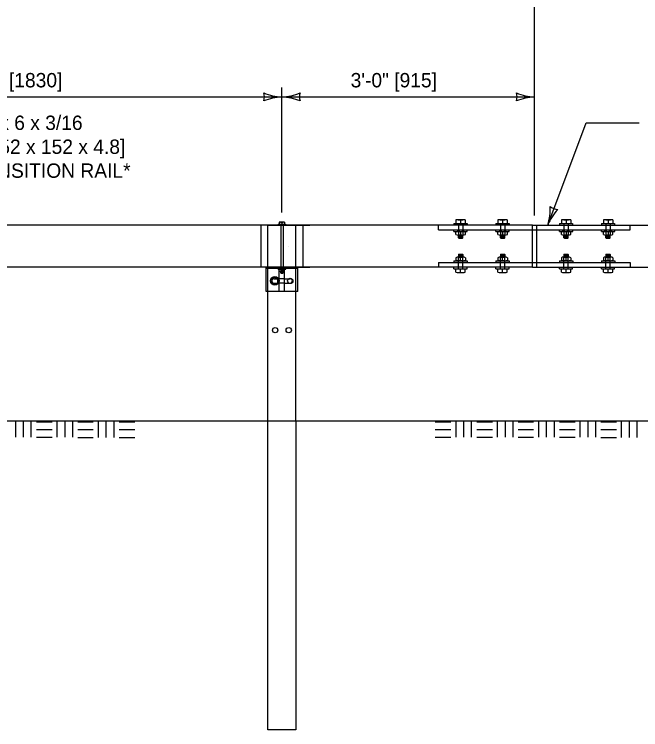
# Model space of a CAD drawing. Extents: x 49983 to 50021, y 49963.5 to 50011.4.
# Drawn here: x 50011.337 to 50013.953, y 49993.178 to 49996.167 of the extents above; entities that cross this region are included whole.
import ezdxf

# ---------------------------------------------------------------- set-up
doc = ezdxf.new("R2010")
doc.units = 0
for name, color, linetype in [('Level 1', 7, 'Continuous'), ('Level 10', 7, 'Continuous'), ('Level 2', 7, 'Continuous'), ('Level 3', 7, 'Continuous'), ('Level 4', 7, 'Continuous')]:
    doc.layers.add(name, color=color, linetype=linetype)

msp = doc.modelspace()

# ---------------------------------------------------------------- linework, layer by layer
at = {"layer": 'Level 1'}
for p, q in [((50013.1811, 49995.3074), (50013.1811, 49995.2927)), ((50013.1908, 49995.3086), (50013.2104, 49995.3086)), ((50013.2006, 49995.3074), (50013.2006, 49995.2927)), ((50013.2202, 49995.3074), (50013.2202, 49995.2927)), ((50013.3564, 49995.3074), (50013.3564, 49995.2927)), ((50013.3662, 49995.3086), (50013.3857, 49995.3086)), ((50013.376, 49995.3074), (50013.376, 49995.2927)), ((50013.3955, 49995.3074), (50013.3955, 49995.2927)), ((50013.6214, 49995.3074), (50013.6214, 49995.2927)), ((50013.6311, 49995.3086), (50013.6507, 49995.3086)), ((50013.6409, 49995.3074), (50013.6409, 49995.2927)), ((50013.6605, 49995.3074), (50013.6605, 49995.2927)), ((50013.7967, 49995.3074), (50013.7967, 49995.2927)), ((50013.8065, 49995.3086), (50013.826, 49995.3086)), ((50013.8163, 49995.3074), (50013.8163, 49995.2927)), ((50013.8358, 49995.3074), (50013.8358, 49995.2927)), ((50013.5013, 49995.2862), (50005.468, 49995.2862)), ((50012.3959, 49995.2862), (50012.5716, 49995.2862)), ((50012.5414, 49995.2862), (50012.4261, 49995.2862)), ((50012.4389, 49995.2899), (50012.4701, 49995.2899)), ((50012.4389, 49995.2899), (50012.4389, 49995.2862)), ((50012.4436, 49995.2981), (50012.4436, 49995.2899)), ((50012.4491, 49995.2988), (50012.4601, 49995.2988)), ((50012.4546, 49995.2981), (50012.4546, 49995.2899)), ((50012.4656, 49995.2981), (50012.4656, 49995.2899)), ((50012.4701, 49995.2899), (50012.4701, 49995.2862)), ((50013.1727, 49995.2927), (50013.2282, 49995.2927)), ((50013.1727, 49995.2927), (50013.1727, 49995.2862)), ((50013.2282, 49995.2927), (50013.2282, 49995.2862)), ((50013.348, 49995.2927), (50013.4035, 49995.2927)), ((50013.348, 49995.2927), (50013.348, 49995.2862)), ((50013.4035, 49995.2927), (50013.4035, 49995.2862)), ((50013.5013, 49995.2862), (50015.1856, 49995.2862)), ((50013.5013, 49995.1105), (50013.5013, 49995.2862)), ((50013.5179, 49995.2862), (50013.5179, 49995.1105)), ((50013.613, 49995.2927), (50013.6685, 49995.2927)), ((50013.613, 49995.2927), (50013.613, 49995.2862)), ((50013.6685, 49995.2927), (50013.6685, 49995.2862)), ((50013.7883, 49995.2927), (50013.8438, 49995.2927)), ((50013.7883, 49995.2927), (50013.7883, 49995.2862)), ((50013.8438, 49995.2927), (50013.8438, 49995.2862)), ((50013.5013, 49995.2666), (50013.5179, 49995.2666)), ((50013.5013, 49995.1302), (50013.5179, 49995.1302)), ((50013.5013, 49995.1105), (50005.468, 49995.1105)), ((50012.3887, 49995.008), (50012.3887, 49995.1105)), ((50012.5205, 49995.105), (50012.3887, 49995.105)), ((50012.3959, 49995.1105), (50012.5716, 49995.1105)), ((50012.4388, 49995.1014), (50012.4388, 49995.1051)), ((50012.4388, 49995.1014), (50012.4703, 49995.1014)), ((50012.4398, 49995.1105), (50012.5716, 49995.1105)), ((50012.4436, 49995.1014), (50012.4436, 49995.0998)), ((50012.4436, 49995.0942), (50012.4436, 49995.0997)), ((50012.4547, 49995.0997), (50012.4547, 49995.0942)), ((50012.4656, 49995.1014), (50012.4656, 49995.0998)), ((50012.4657, 49995.0942), (50012.4657, 49995.0997)), ((50012.4703, 49995.1014), (50012.4703, 49995.1051)), ((50012.5205, 49995.008), (50012.5205, 49995.1105)), ((50013.1727, 49995.104), (50013.1727, 49995.1105)), ((50013.1727, 49995.104), (50013.2282, 49995.104)), ((50013.1811, 49995.0894), (50013.1811, 49995.104)), ((50013.2006, 49995.0894), (50013.2006, 49995.104)), ((50013.2202, 49995.0894), (50013.2202, 49995.104)), ((50013.2282, 49995.104), (50013.2282, 49995.1105)), ((50013.348, 49995.104), (50013.348, 49995.1105)), ((50013.348, 49995.104), (50013.4035, 49995.104)), ((50013.3564, 49995.0894), (50013.3564, 49995.104)), ((50013.376, 49995.0894), (50013.376, 49995.104)), ((50013.3955, 49995.0894), (50013.3955, 49995.104)), ((50013.4035, 49995.104), (50013.4035, 49995.1105)), ((50013.5013, 49995.1105), (50015.1856, 49995.1105)), ((50013.613, 49995.104), (50013.613, 49995.1105)), ((50013.613, 49995.104), (50013.6685, 49995.104)), ((50013.6214, 49995.0894), (50013.6214, 49995.104)), ((50013.6409, 49995.0894), (50013.6409, 49995.104)), ((50013.6605, 49995.0894), (50013.6605, 49995.104)), ((50013.6685, 49995.104), (50013.6685, 49995.1105)), ((50013.7883, 49995.104), (50013.7883, 49995.1105)), ((50013.7883, 49995.104), (50013.8438, 49995.104)), ((50013.7967, 49995.0894), (50013.7967, 49995.104)), ((50013.8163, 49995.0894), (50013.8163, 49995.104)), ((50013.8358, 49995.0894), (50013.8358, 49995.104)), ((50013.8438, 49995.104), (50013.8438, 49995.1105)), ((50012.425, 49995.0678), (50012.4119, 49995.0601)), ((50012.4382, 49995.0601), (50012.425, 49995.0678)), ((50012.4436, 49995.008), (50012.4436, 49995.0941)), ((50012.4491, 49995.0925), (50012.4602, 49995.0925)), ((50012.4495, 49995.0864), (50012.4495, 49995.0925)), ((50012.4598, 49995.0864), (50012.4495, 49995.0864)), ((50012.4495, 49995.0864), (50012.4505, 49995.0853)), ((50012.4505, 49995.0853), (50012.4588, 49995.0853)), ((50012.451, 49995.091), (50012.4582, 49995.091)), ((50012.451, 49995.09), (50012.4582, 49995.09)), ((50012.451, 49995.089), (50012.4582, 49995.089)), ((50012.451, 49995.0879), (50012.4582, 49995.0879)), ((50012.4598, 49995.0864), (50012.4588, 49995.0853)), ((50012.4598, 49995.0864), (50012.4598, 49995.0925)), ((50012.4656, 49995.008), (50012.4656, 49995.0941)), ((50013.1908, 49995.0882), (50013.2104, 49995.0882)), ((50013.3662, 49995.0882), (50013.3857, 49995.0882)), ((50013.6311, 49995.0882), (50013.6507, 49995.0882)), ((50013.8065, 49995.0882), (50013.826, 49995.0882)), ((50012.4119, 49995.0601), (50012.4119, 49995.0453)), ((50012.4119, 49995.0453), (50012.425, 49995.0382)), ((50012.425, 49995.0382), (50012.4382, 49995.0453)), ((50012.4382, 49995.0453), (50012.4382, 49995.0601)), ((50012.4406, 49995.0437), (50012.4436, 49995.0437)), ((50012.4409, 49995.062), (50012.4436, 49995.062)), ((50012.4656, 49995.062), (50012.4889, 49995.062)), ((50012.4656, 49995.0437), (50012.4894, 49995.0437)), ((50012.5205, 49995.008), (50012.3887, 49995.008)), ((50012.3959, 49994.4663), (50012.3959, 49995.008)), ((50012.513, 49994.4663), (50012.513, 49995.008)), ((50015.1755, 49994.4663), (50005.1046, 49994.4663)), ((50011.3431, 49994.3995), (50011.3431, 49994.4645)), ((50011.3756, 49994.3995), (50011.3756, 49994.4645)), ((50011.4081, 49994.3995), (50011.4081, 49994.4645)), ((50011.4297, 49994.4645), (50011.4948, 49994.4645)), ((50011.5165, 49994.3995), (50011.5165, 49994.4645)), ((50011.5489, 49994.3995), (50011.5489, 49994.4645)), ((50011.5814, 49994.3995), (50011.5814, 49994.4645)), ((50011.602, 49994.4643), (50011.667, 49994.4643)), ((50011.6887, 49994.3993), (50011.6887, 49994.4643)), ((50011.7212, 49994.3993), (50011.7212, 49994.4643)), ((50011.7537, 49994.3993), (50011.7537, 49994.4643)), ((50011.7753, 49994.4643), (50011.8404, 49994.4643)), ((50013.0951, 49994.4646), (50013.1601, 49994.4646)), ((50013.1818, 49994.3996), (50013.1818, 49994.4646)), ((50013.2143, 49994.3996), (50013.2143, 49994.4646)), ((50013.2468, 49994.3996), (50013.2468, 49994.4646)), ((50013.2684, 49994.4646), (50013.3335, 49994.4646)), ((50013.3552, 49994.3996), (50013.3552, 49994.4646)), ((50013.3876, 49994.3996), (50013.3876, 49994.4646)), ((50013.4201, 49994.3996), (50013.4201, 49994.4646)), ((50013.4404, 49994.4645), (50013.5054, 49994.4645)), ((50013.5271, 49994.3995), (50013.5271, 49994.4645)), ((50013.5596, 49994.3995), (50013.5596, 49994.4645)), ((50013.5921, 49994.3995), (50013.5921, 49994.4645)), ((50013.6137, 49994.4645), (50013.6788, 49994.4645)), ((50013.7005, 49994.3995), (50013.7005, 49994.4645)), ((50013.7329, 49994.3995), (50013.7329, 49994.4645)), ((50013.7654, 49994.3995), (50013.7654, 49994.4645)), ((50013.786, 49994.4643), (50013.851, 49994.4643)), ((50013.8727, 49994.3993), (50013.8727, 49994.4643)), ((50013.9052, 49994.3993), (50013.9052, 49994.4643)), ((50013.9377, 49994.3993), (50013.9377, 49994.4643)), ((50011.4297, 49994.432), (50011.4948, 49994.432)), ((50011.602, 49994.4318), (50011.667, 49994.4318)), ((50011.7753, 49994.4318), (50011.8404, 49994.4318)), ((50013.0951, 49994.4321), (50013.1601, 49994.4321)), ((50013.2684, 49994.4321), (50013.3335, 49994.4321)), ((50013.4404, 49994.432), (50013.5054, 49994.432)), ((50013.6137, 49994.432), (50013.6788, 49994.432)), ((50013.786, 49994.4318), (50013.851, 49994.4318)), ((50011.4297, 49994.3995), (50011.4948, 49994.3995)), ((50011.602, 49994.3993), (50011.667, 49994.3993)), ((50011.7753, 49994.3993), (50011.8404, 49994.3993)), ((50013.0951, 49994.3996), (50013.1601, 49994.3996)), ((50013.2684, 49994.3996), (50013.3335, 49994.3996)), ((50013.4404, 49994.3995), (50013.5054, 49994.3995)), ((50013.6137, 49994.3995), (50013.6788, 49994.3995)), ((50013.786, 49994.3993), (50013.851, 49994.3993))]:
    msp.add_line(p, q, dxfattribs=at)
for centre, radius in [((50012.4252, 49995.0531), 0.0181), ((50012.4263, 49994.847), 0.011)]:
    msp.add_circle(centre, radius, dxfattribs=at)
for centre, radius, start, end in [((50013.1908, 49995.2675), 0.0411, 76.2307, 103.7693), ((50013.2104, 49995.2675), 0.0411, 76.2307, 103.7693), ((50013.3662, 49995.2675), 0.0411, 76.2307, 103.7693), ((50013.3857, 49995.2675), 0.0411, 76.2307, 103.7693), ((50013.6311, 49995.2675), 0.0411, 76.2307, 103.7693), ((50013.6507, 49995.2675), 0.0411, 76.2307, 103.7693), ((50013.8065, 49995.2675), 0.0411, 76.2307, 103.7693), ((50013.826, 49995.2675), 0.0411, 76.2307, 103.7693), ((50012.4491, 49995.2757), 0.0231, 76.2307, 103.7693), ((50012.4601, 49995.2757), 0.0231, 76.2307, 103.7693), ((50012.4491, 49995.0916), 0.00981, 55.616, 124.384), ((50012.4602, 49995.0916), 0.00981, 55.616, 124.384), ((50012.4491, 49995.1023), 0.00981, 235.616, 304.384), ((50012.4602, 49995.1023), 0.00981, 235.616, 304.384), ((50013.1908, 49995.1293), 0.0411, 256.2307, 283.7693), ((50013.2104, 49995.1293), 0.0411, 256.2307, 283.7693), ((50013.3662, 49995.1293), 0.0411, 256.2307, 283.7693), ((50013.3857, 49995.1293), 0.0411, 256.2307, 283.7693), ((50013.6311, 49995.1293), 0.0411, 256.2307, 283.7693), ((50013.6507, 49995.1293), 0.0411, 256.2307, 283.7693), ((50013.8065, 49995.1293), 0.0411, 256.2307, 283.7693), ((50013.826, 49995.1293), 0.0411, 256.2307, 283.7693), ((50012.4894, 49995.0528), 0.00916, 270, 93.2408)]:
    msp.add_arc(centre, radius, start, end, dxfattribs=at)
at = {"layer": 'Level 10'}
for p, q in [((50012.3959, 49995.008), (50012.3959, 49995.2862)), ((50012.4495, 49995.2899), (50012.4495, 49995.0925)), ((50012.4597, 49995.2899), (50012.4597, 49995.0925)), ((50012.513, 49995.008), (50012.513, 49995.2862)), ((50012.4837, 49995.1984), (50012.4837, 49995.1984)), ((50012.4837, 49995.1984), (50012.4837, 49995.1984)), ((50012.4436, 49995.1014), (50012.4436, 49995.105)), ((50012.4656, 49995.1014), (50012.4656, 49995.105)), ((50012.4198, 49995.0437), (50012.4406, 49995.0437)), ((50012.4203, 49995.062), (50012.4409, 49995.062)), ((50012.4656, 49995.062), (50012.4436, 49995.062)), ((50012.4656, 49995.0437), (50012.4436, 49995.0437))]:
    msp.add_line(p, q, dxfattribs=at)
for centre in [(50012.4894, 49995.0528), (50012.483, 49994.847)]:
    msp.add_circle(centre, 0.011, dxfattribs=at)
msp.add_arc((50012.4198, 49995.0528), 0.00916, 86.7592, 270, dxfattribs=at)
at = {"layer": 'Level 3'}
for p, q in [((50013.5096, 49995.3262), (50013.5096, 49997.0642)), ((50012.4546, 49995.3388), (50012.4546, 49995.8615)), ((50010.3461, 49995.8215), (50012.4546, 49995.8215)), ((50012.4546, 49995.8215), (50013.5096, 49995.8215)), ((50013.5643, 49995.2862), (50013.7246, 49995.7136)), ((50013.7246, 49995.7136), (50013.9458, 49995.7136))]:
    msp.add_line(p, q, dxfattribs=at)
for centre, radius, start, end in [((50012.4638, 49996.0437), 0.2223, 247.456, 267.6395), ((50012.3264, 49995.8215), 0.0548, 342.1388, 17.8612), ((50012.4661, 49995.5888), 0.233, 92.8273, 112.0772), ((50012.4431, 49996.0543), 0.233, 272.8273, 292.0772), ((50012.4455, 49995.5994), 0.2223, 67.456, 87.6395), ((50012.5828, 49995.8215), 0.0548, 162.1388, 197.8612), ((50013.5188, 49996.0437), 0.2223, 247.456, 267.6395), ((50013.3814, 49995.8215), 0.0548, 342.1388, 17.8612), ((50013.5211, 49995.5888), 0.233, 92.8273, 112.0772), ((50013.3423, 49995.3572), 0.233, 342.2587, 1.5085), ((50013.769, 49995.1996), 0.2223, 136.8874, 157.0709), ((50013.6093, 49995.4063), 0.0548, 231.5702, 267.2925)]:
    msp.add_arc(centre, radius, start, end, dxfattribs=at)
at = {"layer": 'Level 4'}
for p, q in [((50012.3668, 49995.2862), (50012.3668, 49995.1105)), ((50012.5425, 49995.2862), (50012.5425, 49995.1105)), ((50013.1083, 49995.2665), (50013.1083, 49995.2862)), ((50013.1917, 49995.2927), (50013.1917, 49995.2441)), ((50013.2099, 49995.2927), (50013.2099, 49995.2441)), ((50013.367, 49995.2927), (50013.367, 49995.2441)), ((50013.3853, 49995.2927), (50013.3853, 49995.2441)), ((50013.632, 49995.2927), (50013.632, 49995.2441)), ((50013.6502, 49995.2927), (50013.6502, 49995.2441)), ((50013.8073, 49995.2927), (50013.8073, 49995.2441)), ((50013.8256, 49995.2927), (50013.8256, 49995.2441)), ((50013.909, 49995.2665), (50013.909, 49995.2862)), ((50013.1082, 49995.2666), (50013.5013, 49995.2666)), ((50013.1727, 49995.26), (50013.1727, 49995.2666)), ((50013.1727, 49995.26), (50013.2285, 49995.26)), ((50013.1811, 49995.2471), (50013.1811, 49995.257)), ((50013.2008, 49995.257), (50013.2008, 49995.2471)), ((50013.2205, 49995.2471), (50013.2205, 49995.257)), ((50013.2285, 49995.26), (50013.2285, 49995.2666)), ((50013.348, 49995.26), (50013.348, 49995.2666)), ((50013.348, 49995.26), (50013.4039, 49995.26)), ((50013.3565, 49995.2471), (50013.3565, 49995.257)), ((50013.3762, 49995.257), (50013.3762, 49995.2471)), ((50013.3958, 49995.2471), (50013.3958, 49995.257)), ((50013.4039, 49995.26), (50013.4039, 49995.2666)), ((50013.5179, 49995.2666), (50013.909, 49995.2666)), ((50013.613, 49995.26), (50013.613, 49995.2666)), ((50013.613, 49995.26), (50013.6688, 49995.26)), ((50013.6214, 49995.2471), (50013.6214, 49995.257)), ((50013.6411, 49995.257), (50013.6411, 49995.2471)), ((50013.6608, 49995.2471), (50013.6608, 49995.257)), ((50013.6688, 49995.26), (50013.6688, 49995.2666)), ((50013.7883, 49995.26), (50013.7883, 49995.2666)), ((50013.7883, 49995.26), (50013.8442, 49995.26)), ((50013.7968, 49995.2471), (50013.7968, 49995.257)), ((50013.8165, 49995.257), (50013.8165, 49995.2471)), ((50013.8361, 49995.2471), (50013.8361, 49995.257)), ((50013.8442, 49995.26), (50013.8442, 49995.2666)), ((50013.191, 49995.2441), (50013.2107, 49995.2441)), ((50013.1917, 49995.2332), (50013.1917, 49995.2441)), ((50013.2099, 49995.2332), (50013.1917, 49995.2332)), ((50013.1917, 49995.2332), (50013.1935, 49995.2314)), ((50013.1935, 49995.2314), (50013.2081, 49995.2314)), ((50013.1943, 49995.2415), (50013.2072, 49995.2415)), ((50013.1943, 49995.2397), (50013.2072, 49995.2397)), ((50013.1943, 49995.2378), (50013.2072, 49995.2378)), ((50013.1943, 49995.236), (50013.2072, 49995.236)), ((50013.2099, 49995.2332), (50013.2081, 49995.2314)), ((50013.2099, 49995.2332), (50013.2099, 49995.2441)), ((50013.3663, 49995.2441), (50013.386, 49995.2441)), ((50013.367, 49995.2332), (50013.367, 49995.2441)), ((50013.3853, 49995.2332), (50013.367, 49995.2332)), ((50013.367, 49995.2332), (50013.3689, 49995.2314)), ((50013.3689, 49995.2314), (50013.3835, 49995.2314)), ((50013.3697, 49995.2415), (50013.3825, 49995.2415)), ((50013.3697, 49995.2397), (50013.3825, 49995.2397)), ((50013.3697, 49995.2378), (50013.3825, 49995.2378)), ((50013.3697, 49995.236), (50013.3825, 49995.236)), ((50013.3853, 49995.2332), (50013.3835, 49995.2314)), ((50013.3853, 49995.2332), (50013.3853, 49995.2441)), ((50013.6313, 49995.2441), (50013.6509, 49995.2441)), ((50013.632, 49995.2332), (50013.632, 49995.2441)), ((50013.6502, 49995.2332), (50013.632, 49995.2332)), ((50013.632, 49995.2332), (50013.6338, 49995.2314)), ((50013.6338, 49995.2314), (50013.6484, 49995.2314)), ((50013.6346, 49995.2415), (50013.6475, 49995.2415)), ((50013.6346, 49995.2397), (50013.6475, 49995.2397)), ((50013.6346, 49995.2378), (50013.6475, 49995.2378)), ((50013.6346, 49995.236), (50013.6475, 49995.236)), ((50013.6502, 49995.2332), (50013.6484, 49995.2314)), ((50013.6502, 49995.2332), (50013.6502, 49995.2441)), ((50013.8066, 49995.2441), (50013.8263, 49995.2441)), ((50013.8073, 49995.2332), (50013.8073, 49995.2441)), ((50013.8256, 49995.2332), (50013.8073, 49995.2332)), ((50013.8073, 49995.2332), (50013.8091, 49995.2314)), ((50013.8091, 49995.2314), (50013.8238, 49995.2314)), ((50013.81, 49995.2415), (50013.8228, 49995.2415)), ((50013.81, 49995.2397), (50013.8228, 49995.2397)), ((50013.81, 49995.2378), (50013.8228, 49995.2378)), ((50013.81, 49995.236), (50013.8228, 49995.236)), ((50013.8256, 49995.2332), (50013.8238, 49995.2314)), ((50013.8256, 49995.2332), (50013.8256, 49995.2441)), ((50013.1917, 49995.1635), (50013.1935, 49995.1653)), ((50013.1917, 49995.1635), (50013.1917, 49995.1527)), ((50013.2099, 49995.1635), (50013.1917, 49995.1635)), ((50013.1935, 49995.1653), (50013.2081, 49995.1653)), ((50013.1943, 49995.1607), (50013.2072, 49995.1607)), ((50013.1943, 49995.1589), (50013.2072, 49995.1589)), ((50013.1943, 49995.1571), (50013.2072, 49995.1571)), ((50013.2099, 49995.1635), (50013.2081, 49995.1653)), ((50013.2099, 49995.1635), (50013.2099, 49995.1527)), ((50013.367, 49995.1635), (50013.3689, 49995.1653)), ((50013.367, 49995.1635), (50013.367, 49995.1527)), ((50013.3853, 49995.1635), (50013.367, 49995.1635)), ((50013.3689, 49995.1653), (50013.3835, 49995.1653)), ((50013.3697, 49995.1607), (50013.3825, 49995.1607)), ((50013.3697, 49995.1589), (50013.3825, 49995.1589)), ((50013.3697, 49995.1571), (50013.3825, 49995.1571)), ((50013.3853, 49995.1635), (50013.3835, 49995.1653)), ((50013.3853, 49995.1635), (50013.3853, 49995.1527)), ((50013.632, 49995.1635), (50013.6338, 49995.1653)), ((50013.632, 49995.1635), (50013.632, 49995.1527)), ((50013.6502, 49995.1635), (50013.632, 49995.1635)), ((50013.6338, 49995.1653), (50013.6484, 49995.1653)), ((50013.6346, 49995.1607), (50013.6475, 49995.1607)), ((50013.6346, 49995.1589), (50013.6475, 49995.1589)), ((50013.6346, 49995.1571), (50013.6475, 49995.1571)), ((50013.6502, 49995.1635), (50013.6484, 49995.1653)), ((50013.6502, 49995.1635), (50013.6502, 49995.1527)), ((50013.8073, 49995.1635), (50013.8091, 49995.1653)), ((50013.8073, 49995.1635), (50013.8073, 49995.1527)), ((50013.8256, 49995.1635), (50013.8073, 49995.1635)), ((50013.8091, 49995.1653), (50013.8238, 49995.1653)), ((50013.81, 49995.1607), (50013.8228, 49995.1607)), ((50013.81, 49995.1589), (50013.8228, 49995.1589)), ((50013.81, 49995.1571), (50013.8228, 49995.1571)), ((50013.8256, 49995.1635), (50013.8238, 49995.1653)), ((50013.8256, 49995.1635), (50013.8256, 49995.1527)), ((50013.1083, 49995.1302), (50013.1083, 49995.1105)), ((50013.1083, 49995.1302), (50013.5013, 49995.1302)), ((50013.1727, 49995.1367), (50013.2285, 49995.1367)), ((50013.1727, 49995.1367), (50013.1727, 49995.1302)), ((50013.1811, 49995.1496), (50013.1811, 49995.1398)), ((50013.191, 49995.1527), (50013.2107, 49995.1527)), ((50013.1917, 49995.104), (50013.1917, 49995.1527)), ((50013.1943, 49995.1552), (50013.2072, 49995.1552)), ((50013.2008, 49995.1398), (50013.2008, 49995.1496)), ((50013.2099, 49995.104), (50013.2099, 49995.1527)), ((50013.2205, 49995.1496), (50013.2205, 49995.1398)), ((50013.2285, 49995.1367), (50013.2285, 49995.1302)), ((50013.348, 49995.1367), (50013.4039, 49995.1367)), ((50013.348, 49995.1367), (50013.348, 49995.1302)), ((50013.3565, 49995.1496), (50013.3565, 49995.1398)), ((50013.3663, 49995.1527), (50013.386, 49995.1527)), ((50013.367, 49995.104), (50013.367, 49995.1527)), ((50013.3697, 49995.1552), (50013.3825, 49995.1552)), ((50013.3762, 49995.1398), (50013.3762, 49995.1496)), ((50013.3853, 49995.104), (50013.3853, 49995.1527)), ((50013.3958, 49995.1496), (50013.3958, 49995.1398)), ((50013.4039, 49995.1367), (50013.4039, 49995.1302)), ((50013.5179, 49995.1302), (50013.909, 49995.1302)), ((50013.613, 49995.1367), (50013.6688, 49995.1367)), ((50013.613, 49995.1367), (50013.613, 49995.1302)), ((50013.6214, 49995.1496), (50013.6214, 49995.1398)), ((50013.6313, 49995.1527), (50013.6509, 49995.1527)), ((50013.632, 49995.104), (50013.632, 49995.1527)), ((50013.6346, 49995.1552), (50013.6475, 49995.1552)), ((50013.6411, 49995.1398), (50013.6411, 49995.1496)), ((50013.6502, 49995.104), (50013.6502, 49995.1527)), ((50013.6608, 49995.1496), (50013.6608, 49995.1398)), ((50013.6688, 49995.1367), (50013.6688, 49995.1302)), ((50013.7883, 49995.1367), (50013.8442, 49995.1367)), ((50013.7883, 49995.1367), (50013.7883, 49995.1302)), ((50013.7968, 49995.1496), (50013.7968, 49995.1398)), ((50013.8066, 49995.1527), (50013.8263, 49995.1527)), ((50013.8073, 49995.104), (50013.8073, 49995.1527)), ((50013.81, 49995.1552), (50013.8228, 49995.1552)), ((50013.8165, 49995.1398), (50013.8165, 49995.1496)), ((50013.8256, 49995.104), (50013.8256, 49995.1527)), ((50013.8361, 49995.1496), (50013.8361, 49995.1398)), ((50013.8442, 49995.1367), (50013.8442, 49995.1302)), ((50013.909, 49995.1302), (50013.909, 49995.1105)), ((50012.3959, 49993.1779), (50012.3959, 49994.4663)), ((50012.513, 49994.4663), (50012.513, 49993.1779)), ((50012.513, 49993.1779), (50012.3959, 49993.1779))]:
    msp.add_line(p, q, dxfattribs=at)
for centre, start, end in [((50013.191, 49995.2426), 55.616, 124.384), ((50013.191, 49995.2615), 235.616, 304.384), ((50013.2107, 49995.2426), 55.616, 124.384), ((50013.2107, 49995.2615), 235.616, 304.384), ((50013.3663, 49995.2426), 55.616, 124.384), ((50013.3663, 49995.2615), 235.616, 304.384), ((50013.386, 49995.2426), 55.616, 124.384), ((50013.386, 49995.2615), 235.616, 304.384), ((50013.6313, 49995.2426), 55.616, 124.384), ((50013.6313, 49995.2615), 235.616, 304.384), ((50013.6509, 49995.2426), 55.616, 124.384), ((50013.6509, 49995.2615), 235.616, 304.384), ((50013.8066, 49995.2426), 55.616, 124.384), ((50013.8066, 49995.2615), 235.616, 304.384), ((50013.8263, 49995.2426), 55.616, 124.384), ((50013.8263, 49995.2615), 235.616, 304.384), ((50013.191, 49995.1352), 55.616, 124.384), ((50013.191, 49995.1542), 235.616, 304.384), ((50013.2107, 49995.1352), 55.616, 124.384), ((50013.2107, 49995.1542), 235.616, 304.384), ((50013.3663, 49995.1352), 55.616, 124.384), ((50013.3663, 49995.1542), 235.616, 304.384), ((50013.386, 49995.1352), 55.616, 124.384), ((50013.386, 49995.1542), 235.616, 304.384), ((50013.6313, 49995.1352), 55.616, 124.384), ((50013.6313, 49995.1542), 235.616, 304.384), ((50013.6509, 49995.1352), 55.616, 124.384), ((50013.6509, 49995.1542), 235.616, 304.384), ((50013.8066, 49995.1352), 55.616, 124.384), ((50013.8066, 49995.1542), 235.616, 304.384), ((50013.8263, 49995.1352), 55.616, 124.384), ((50013.8263, 49995.1542), 235.616, 304.384)]:
    msp.add_arc(centre, 0.0174, start, end, dxfattribs=at)

# ---------------------------------------------------------------- texts
at = {"layer": 'Level 2'}
for s, p in [('6\'-0" [1830]', (50011.1328, 49995.8615)), ('3\'-0" [915]', (50012.7415, 49995.8615)), ('TS6 x 6 x 3/16', (50011.105, 49995.6836)), ('[TS152 x 152 x 4.8]', (50011.105, 49995.5836)), ('TRANSITION RAIL*', (50011.105, 49995.4836))]:
    msp.add_text(s, height=0.06, dxfattribs=at).set_placement(p)

doc.saveas('drawing.dxf')
